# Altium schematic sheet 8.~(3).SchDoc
size 609 x 444 mm
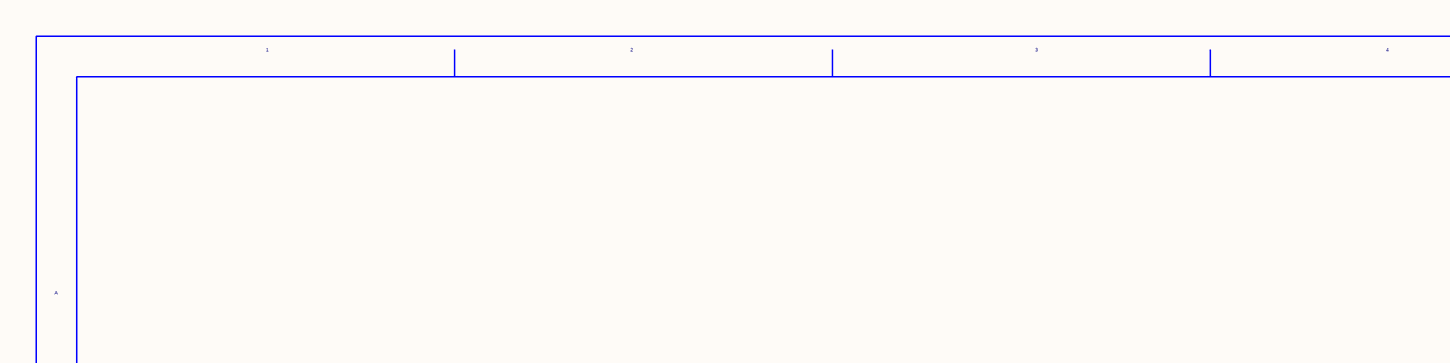
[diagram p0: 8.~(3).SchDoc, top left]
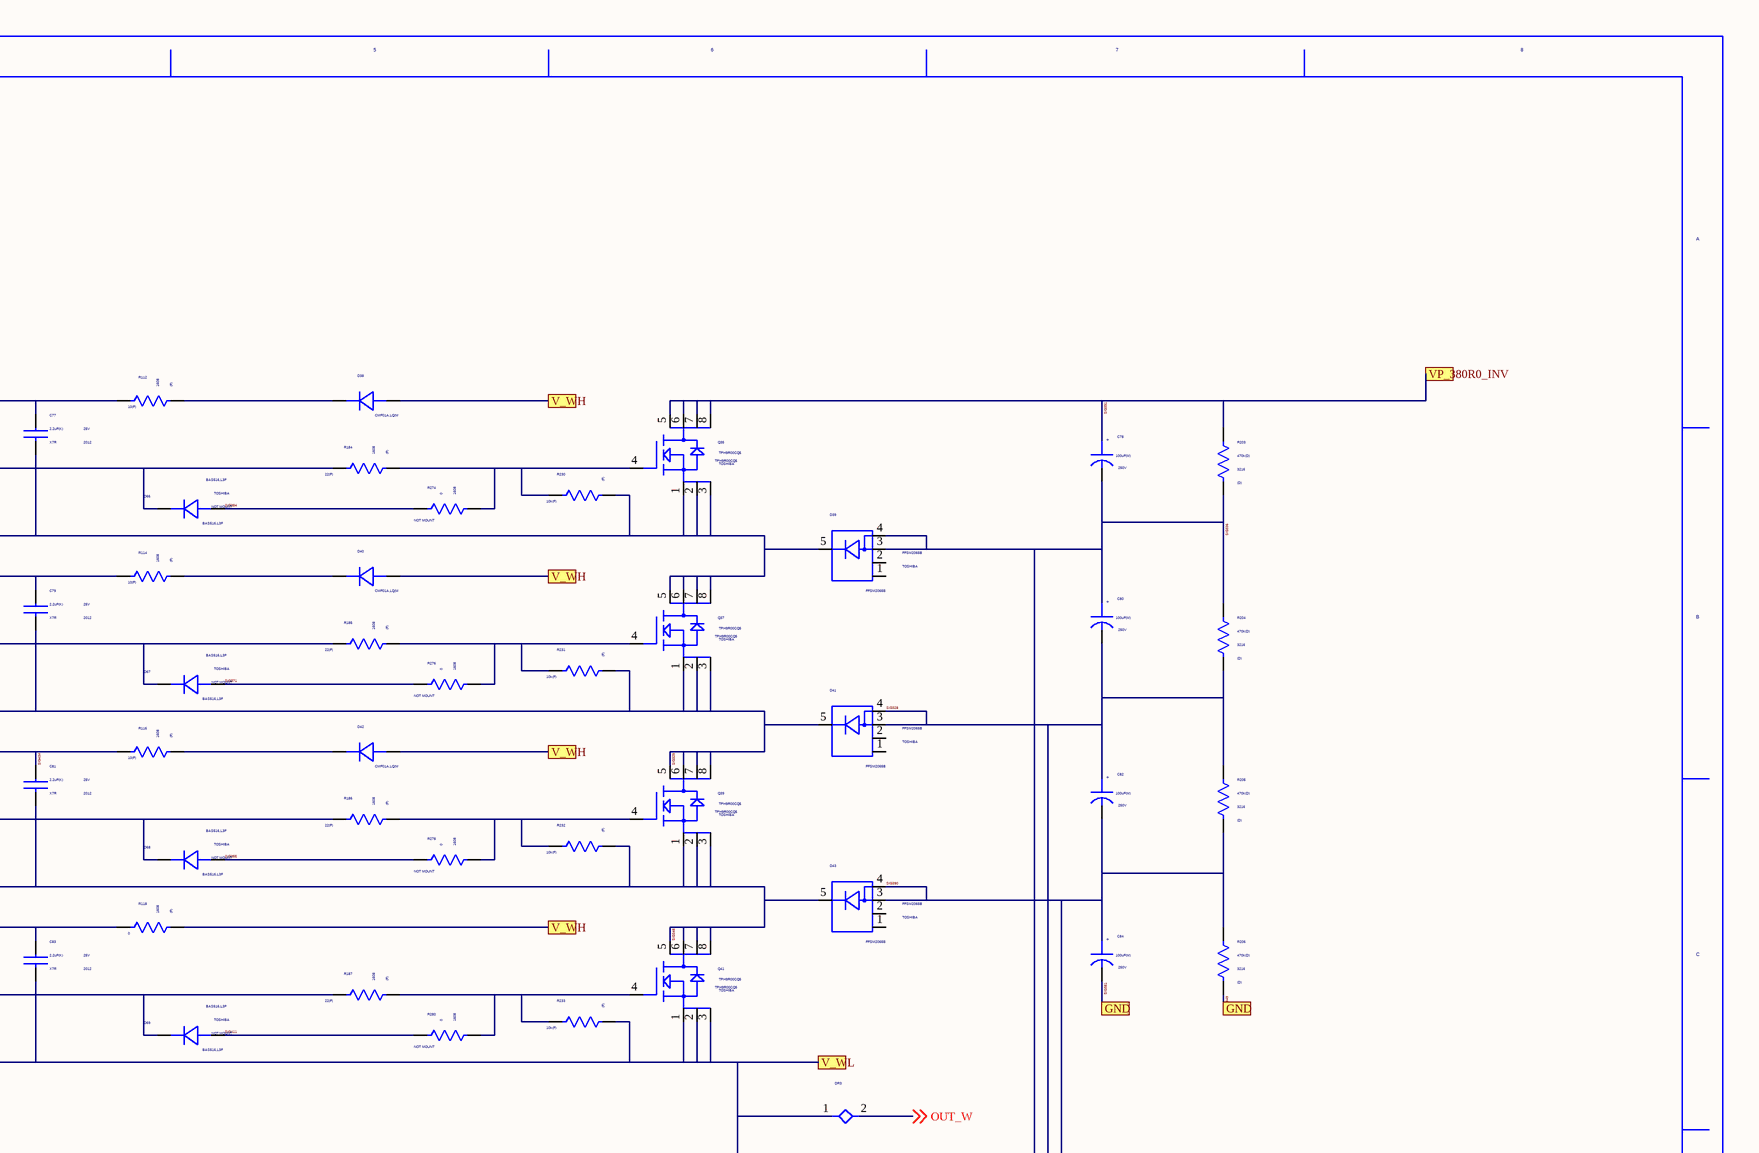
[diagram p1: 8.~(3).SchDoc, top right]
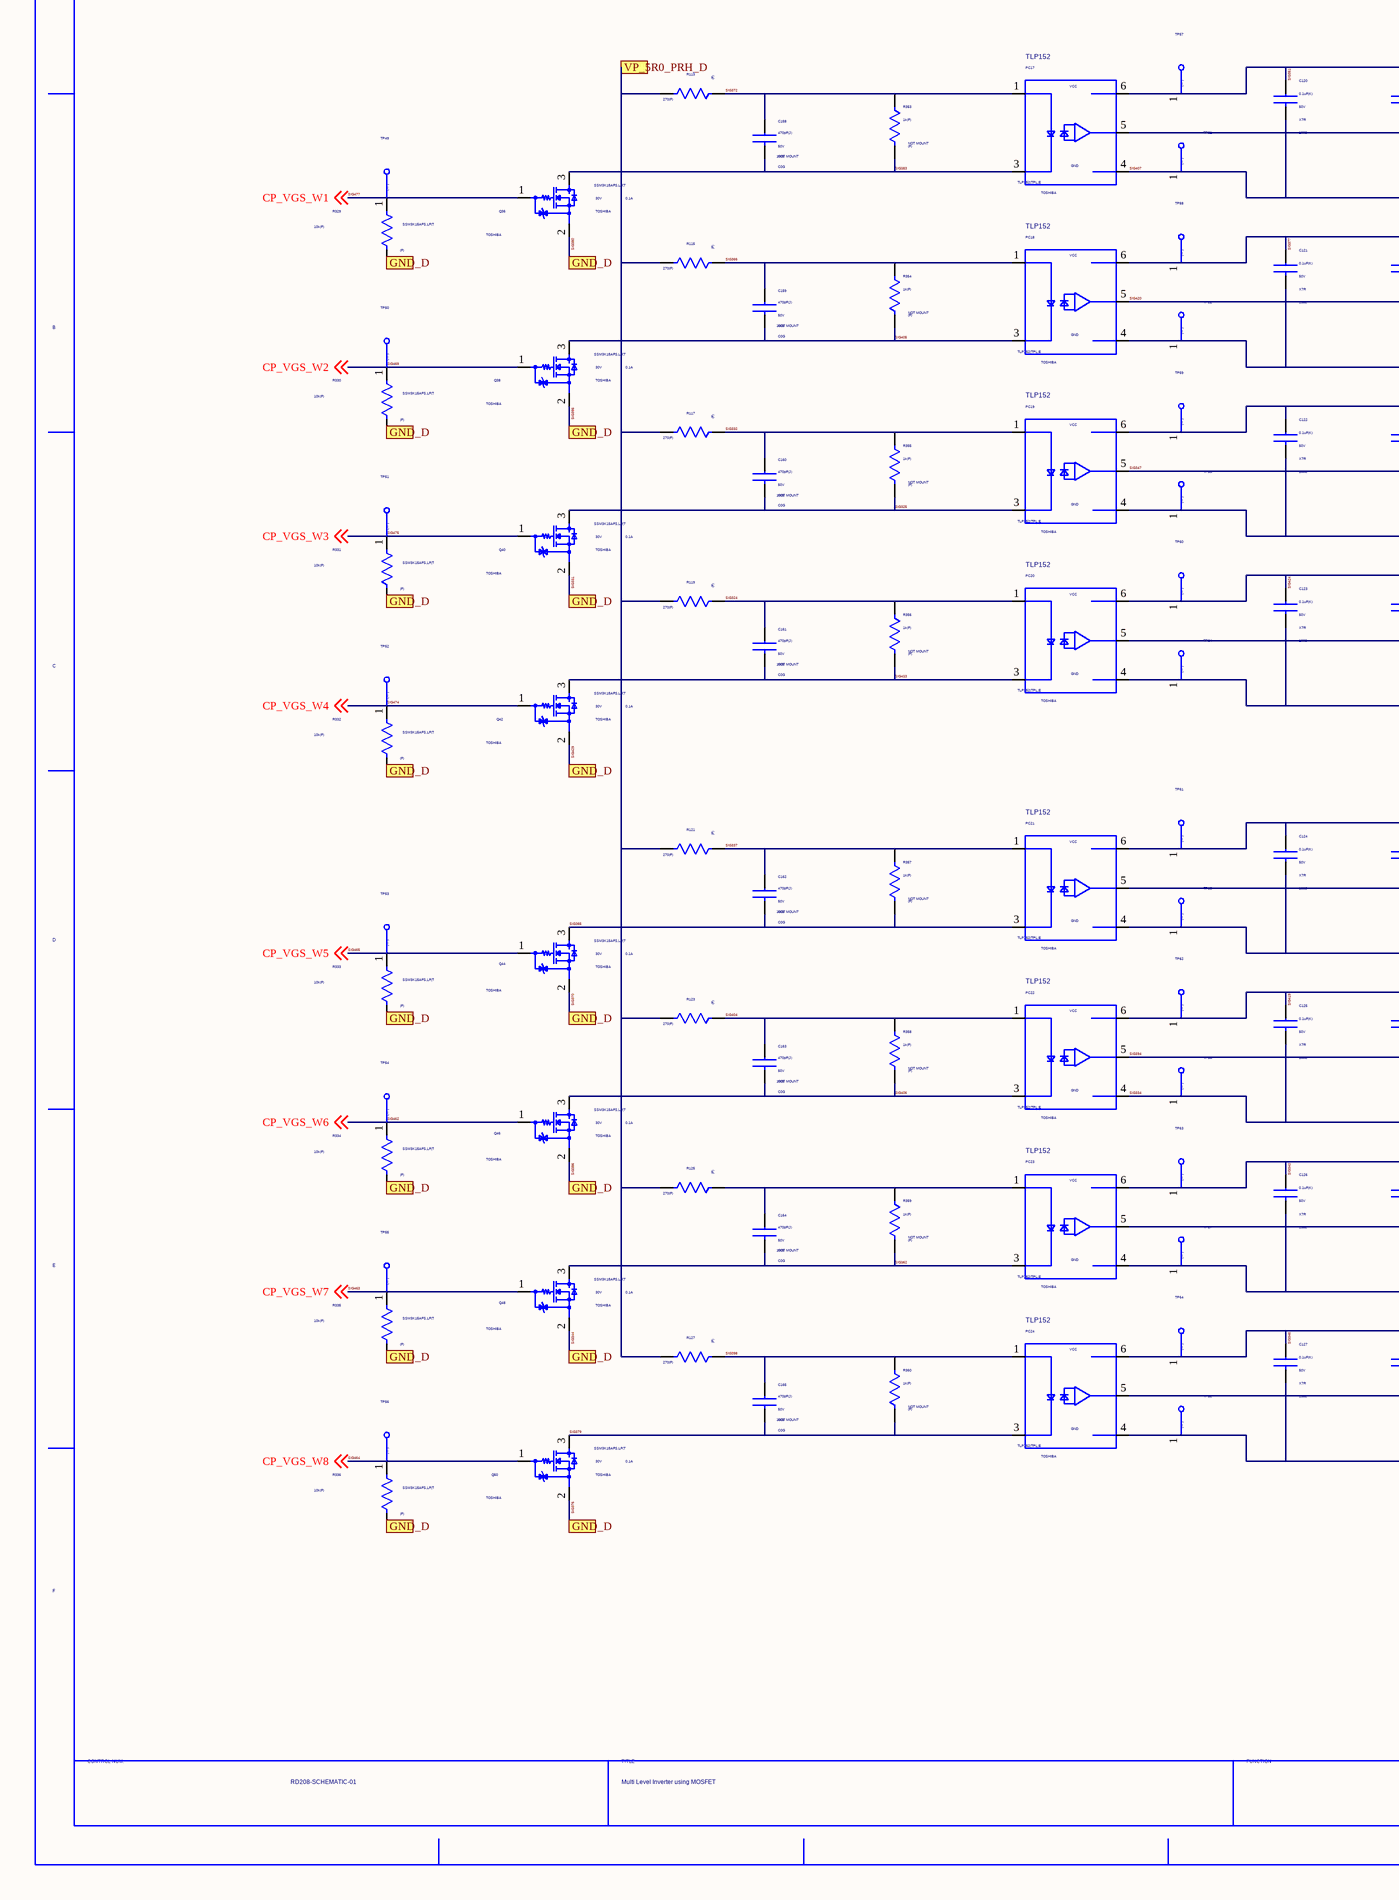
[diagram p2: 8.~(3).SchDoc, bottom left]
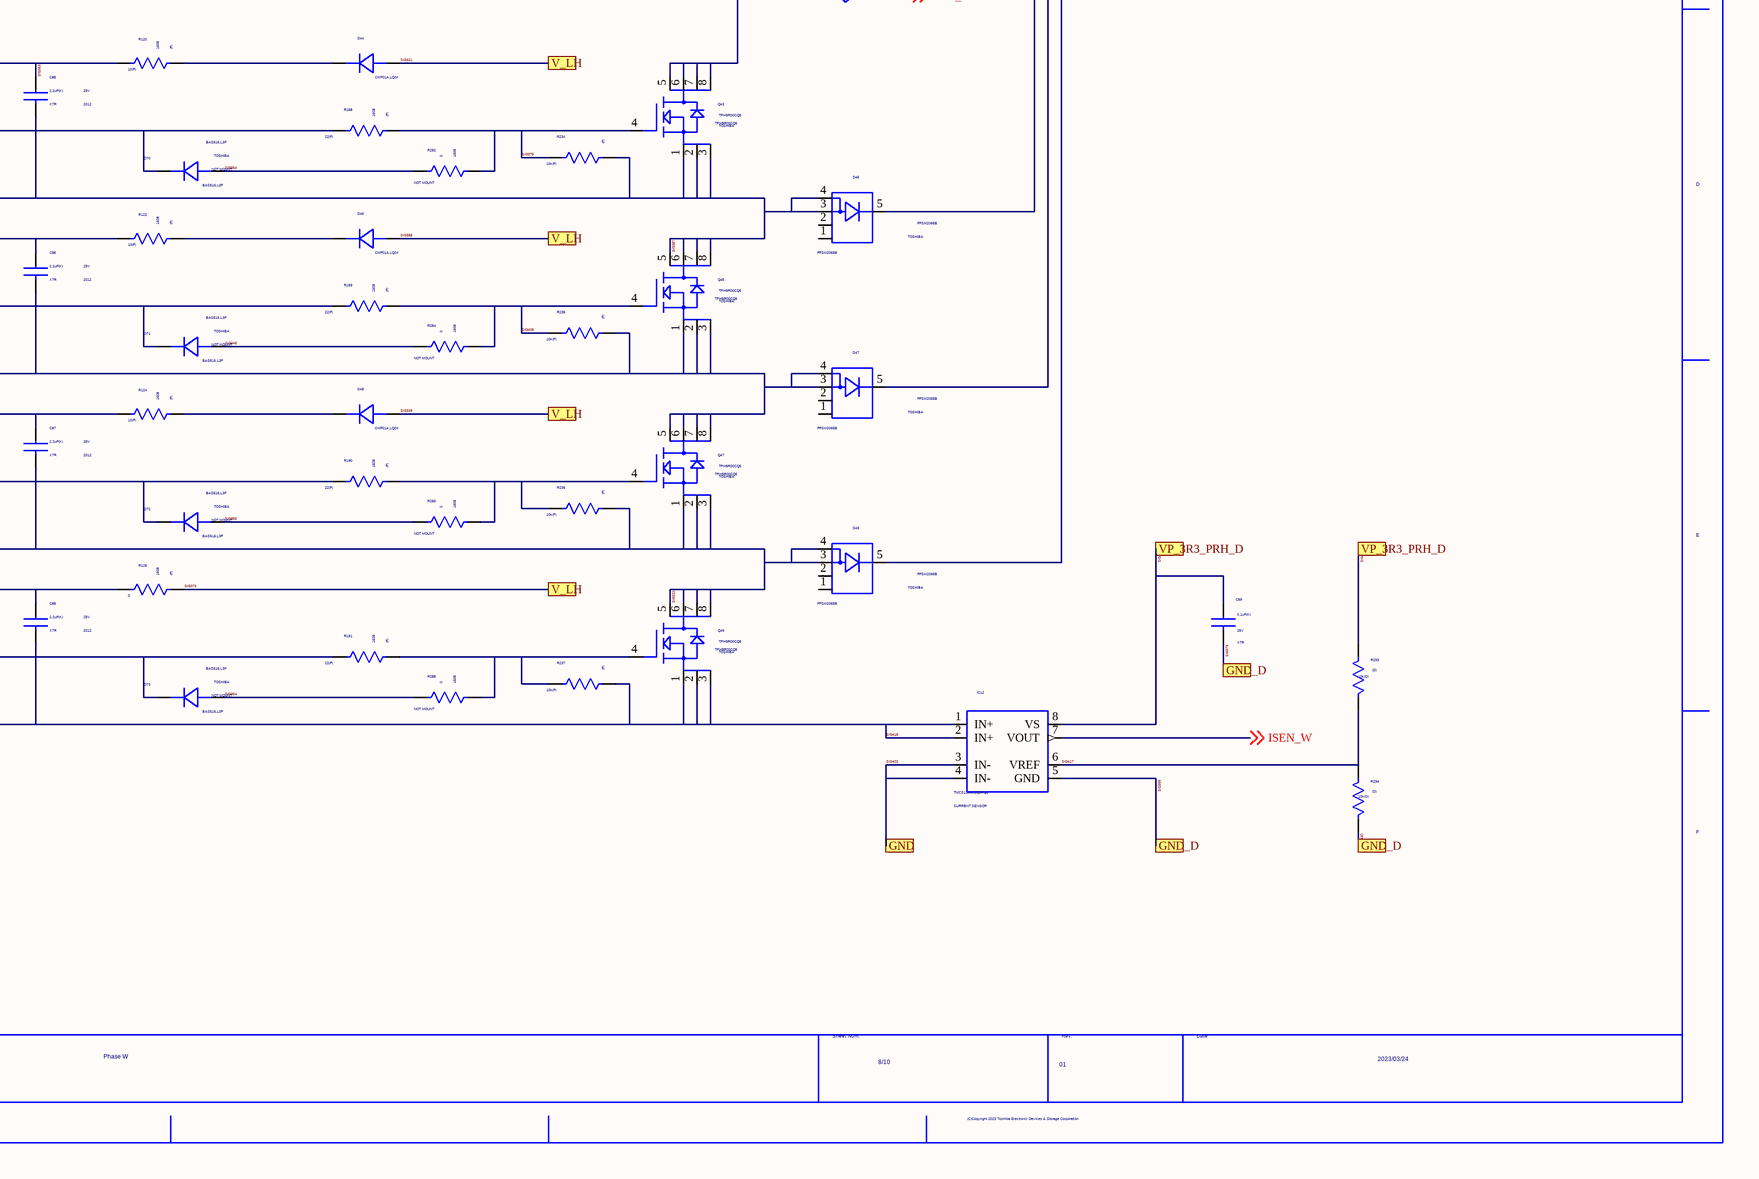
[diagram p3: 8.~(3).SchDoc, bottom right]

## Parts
C77  VAL2: 25V  SIZECODESMD: 2012  VALUE4: X7R  VAL1: 2.2uF(K)  (hidden comment: GRM21BR71E225KE11L)
C78  VAL2: 250V  VAL1: 100uF(M)  (hidden comment: EKMQ251ELL101ML25S)
C79  VAL2: 25V  SIZECODESMD: 2012  VALUE4: X7R  VAL1: 2.2uF(K)  (hidden comment: GRM21BR71E225KE11L)
C80  VAL2: 250V  VAL1: 100uF(M)  (hidden comment: EKMQ251ELL101ML25S)
C81  VAL2: 25V  SIZECODESMD: 2012  VALUE4: X7R  VAL1: 2.2uF(K)  (hidden comment: GRM21BR71E225KE11L)
C82  VAL2: 250V  VAL1: 100uF(M)  (hidden comment: EKMQ251ELL101ML25S)
C83  VAL2: 25V  SIZECODESMD: 2012  VALUE4: X7R  VAL1: 2.2uF(K)  (hidden comment: GRM21BR71E225KE11L)
C84  VAL2: 250V  VAL1: 100uF(M)  (hidden comment: EKMQ251ELL101ML25S)
C85  VAL2: 25V  SIZECODESMD: 2012  VALUE4: X7R  VAL1: 2.2uF(K)  (hidden comment: GRM21BR71E225KE11L)
C86  VAL2: 25V  SIZECODESMD: 2012  VALUE4: X7R  VAL1: 2.2uF(K)  (hidden comment: GRM21BR71E225KE11L)
C87  VAL2: 25V  SIZECODESMD: 2012  VALUE4: X7R  VAL1: 2.2uF(K)  (hidden comment: GRM21BR71E225KE11L)
C88  VAL2: 25V  SIZECODESMD: 2012  VALUE4: X7R  VAL1: 2.2uF(K)  (hidden comment: GRM21BR71E225KE11L)
C89  VAL2: 25V  VALUE4: X7R  VAL1: 0.1uF(K)  (hidden comment: GRM155R71E104KE14D)
C120  VAL2: 50V  SIZECODESMD: 1608  VALUE4: X7R  VAL1: 0.1uF(K)  (hidden comment: C1608X7R1H104K080AA)
C121  VAL2: 50V  SIZECODESMD: 1608  VALUE4: X7R  VAL1: 0.1uF(K)  (hidden comment: C1608X7R1H104K080AA)
C122  VAL2: 50V  SIZECODESMD: 1608  VALUE4: X7R  VAL1: 0.1uF(K)  (hidden comment: C1608X7R1H104K080AA)
C123  VAL2: 50V  SIZECODESMD: 1608  VALUE4: X7R  VAL1: 0.1uF(K)  (hidden comment: C1608X7R1H104K080AA)
C124  VAL2: 50V  SIZECODESMD: 1608  VALUE4: X7R  VAL1: 0.1uF(K)  (hidden comment: C1608X7R1H104K080AA)
C125  VAL2: 50V  SIZECODESMD: 1608  VALUE4: X7R  VAL1: 0.1uF(K)  (hidden comment: C1608X7R1H104K080AA)
C126  VAL2: 50V  SIZECODESMD: 1608  VALUE4: X7R  VAL1: 0.1uF(K)  (hidden comment: C1608X7R1H104K080AA)
C127  VAL2: 50V  SIZECODESMD: 1608  VALUE4: X7R  VAL1: 0.1uF(K)  (hidden comment: C1608X7R1H104K080AA)
C158  VAL2: 50V  SIZECODESMD: 1005  VALUE4: C0G  VAL1: 470pF(J)  NOTMOUNT: NOT MOUNT  (hidden comment: GRM1555C1H471JA01J)
C159  VAL2: 50V  SIZECODESMD: 1005  VALUE4: C0G  VAL1: 470pF(J)  NOTMOUNT: NOT MOUNT  (hidden comment: GRM1555C1H471JA01J)
C160  VAL2: 50V  SIZECODESMD: 1005  VALUE4: C0G  VAL1: 470pF(J)  NOTMOUNT: NOT MOUNT  (hidden comment: GRM1555C1H471JA01J)
C161  VAL2: 50V  SIZECODESMD: 1005  VALUE4: C0G  VAL1: 470pF(J)  NOTMOUNT: NOT MOUNT  (hidden comment: GRM1555C1H471JA01J)
C162  VAL2: 50V  SIZECODESMD: 1005  VALUE4: C0G  VAL1: 470pF(J)  NOTMOUNT: NOT MOUNT  (hidden comment: GRM1555C1H471JA01J)
C163  VAL2: 50V  SIZECODESMD: 1005  VALUE4: C0G  VAL1: 470pF(J)  NOTMOUNT: NOT MOUNT  (hidden comment: GRM1555C1H471JA01J)
C164  VAL2: 50V  SIZECODESMD: 1005  VALUE4: C0G  VAL1: 470pF(J)  NOTMOUNT: NOT MOUNT  (hidden comment: GRM1555C1H471JA01J)
C165  VAL2: 50V  SIZECODESMD: 1005  VALUE4: C0G  VAL1: 470pF(J)  NOTMOUNT: NOT MOUNT  (hidden comment: GRM1555C1H471JA01J)
D38  VAL1: CMF01A,LQ(M  (hidden comment: CMF01A,LQ_M)
D39  USERCOMPTEXT3: TOSHIBA  (hidden comment: FFSM2065B)
D40  VAL1: CMF01A,LQ(M  (hidden comment: CMF01A,LQ_M)
D41  USERCOMPTEXT3: TOSHIBA  (hidden comment: FFSM2065B)
D42  VAL1: CMF01A,LQ(M  (hidden comment: CMF01A,LQ_M)
D43  USERCOMPTEXT3: TOSHIBA  (hidden comment: FFSM2065B)
D44  VAL1: CMF01A,LQ(M  (hidden comment: CMF01A,LQ_M)
D45  USERCOMPTEXT3: TOSHIBA  (hidden comment: FFSM2065B)
D46  VAL1: CMF01A,LQ(M  (hidden comment: CMF01A,LQ_M)
D47  USERCOMPTEXT3: TOSHIBA  (hidden comment: FFSM2065B)
D48  VAL1: CMF01A,LQ(M  (hidden comment: CMF01A,LQ_M)
D49  USERCOMPTEXT3: TOSHIBA  (hidden comment: FFSM2065B)
D66  USERCOMPTEXT3: TOSHIBA  NOTMOUNT: NOT MOUNT  (hidden comment: BAS516,L3F)
D67  USERCOMPTEXT3: TOSHIBA  NOTMOUNT: NOT MOUNT  (hidden comment: BAS516,L3F)
D68  USERCOMPTEXT3: TOSHIBA  NOTMOUNT: NOT MOUNT  (hidden comment: BAS516,L3F)
D69  USERCOMPTEXT3: TOSHIBA  NOTMOUNT: NOT MOUNT  (hidden comment: BAS516,L3F)
D70  USERCOMPTEXT3: TOSHIBA  NOTMOUNT: NOT MOUNT  (hidden comment: BAS516,L3F)
D71  USERCOMPTEXT3: TOSHIBA  NOTMOUNT: NOT MOUNT  (hidden comment: BAS516,L3F)
D72  USERCOMPTEXT3: TOSHIBA  NOTMOUNT: NOT MOUNT  (hidden comment: BAS516,L3F)
D73  USERCOMPTEXT3: TOSHIBA  NOTMOUNT: NOT MOUNT  (hidden comment: BAS516,L3F)
DR3  STAR2  (value not drawn)
IC12  VAL2: CURRENT SENSOR  (hidden comment: TMCS1100A1QDRQ1)
PC17  SCH_NAME: TLP152  USERCOMPTEXT3: TOSHIBA  VAL3: TLP152(TPL,E  (hidden comment: TLP152_TPL,E)
PC18  SCH_NAME: TLP152  USERCOMPTEXT3: TOSHIBA  VAL3: TLP152(TPL,E  (hidden comment: TLP152_TPL,E)
PC19  SCH_NAME: TLP152  USERCOMPTEXT3: TOSHIBA  VAL3: TLP152(TPL,E  (hidden comment: TLP152_TPL,E)
PC20  SCH_NAME: TLP152  USERCOMPTEXT3: TOSHIBA  VAL3: TLP152(TPL,E  (hidden comment: TLP152_TPL,E)
PC21  SCH_NAME: TLP152  USERCOMPTEXT3: TOSHIBA  VAL3: TLP152(TPL,E  (hidden comment: TLP152_TPL,E)
PC22  SCH_NAME: TLP152  USERCOMPTEXT3: TOSHIBA  VAL3: TLP152(TPL,E  (hidden comment: TLP152_TPL,E)
PC23  SCH_NAME: TLP152  USERCOMPTEXT3: TOSHIBA  VAL3: TLP152(TPL,E  (hidden comment: TLP152_TPL,E)
PC24  SCH_NAME: TLP152  USERCOMPTEXT3: TOSHIBA  VAL3: TLP152(TPL,E  (hidden comment: TLP152_TPL,E)
Q35  USERCOMPTEXT3: TOSHIBA  (hidden comment: TPH9R00CQ5)
Q36  VAL2: 0.1A  MANUFACTURER: TOSHIBA  SIZECODESMD: 30V  VAL1: SSM3K15AFS,LF(T  (hidden comment: SSM3K15AFS,LF_T)
Q37  USERCOMPTEXT3: TOSHIBA  (hidden comment: TPH9R00CQ5)
Q38  VAL2: 0.1A  MANUFACTURER: TOSHIBA  SIZECODESMD: 30V  VAL1: SSM3K15AFS,LF(T  (hidden comment: SSM3K15AFS,LF_T)
Q39  USERCOMPTEXT3: TOSHIBA  (hidden comment: TPH9R00CQ5)
Q40  VAL2: 0.1A  MANUFACTURER: TOSHIBA  SIZECODESMD: 30V  VAL1: SSM3K15AFS,LF(T  (hidden comment: SSM3K15AFS,LF_T)
Q41  USERCOMPTEXT3: TOSHIBA  (hidden comment: TPH9R00CQ5)
Q42  VAL2: 0.1A  MANUFACTURER: TOSHIBA  SIZECODESMD: 30V  VAL1: SSM3K15AFS,LF(T  (hidden comment: SSM3K15AFS,LF_T)
Q43  USERCOMPTEXT3: TOSHIBA  (hidden comment: TPH9R00CQ5)
Q44  VAL2: 0.1A  MANUFACTURER: TOSHIBA  SIZECODESMD: 30V  VAL1: SSM3K15AFS,LF(T  (hidden comment: SSM3K15AFS,LF_T)
Q45  USERCOMPTEXT3: TOSHIBA  (hidden comment: TPH9R00CQ5)
Q46  VAL2: 0.1A  MANUFACTURER: TOSHIBA  SIZECODESMD: 30V  VAL1: SSM3K15AFS,LF(T  (hidden comment: SSM3K15AFS,LF_T)
Q47  USERCOMPTEXT3: TOSHIBA  (hidden comment: TPH9R00CQ5)
Q48  VAL2: 0.1A  MANUFACTURER: TOSHIBA  SIZECODESMD: 30V  VAL1: SSM3K15AFS,LF(T  (hidden comment: SSM3K15AFS,LF_T)
Q49  USERCOMPTEXT3: TOSHIBA  (hidden comment: TPH9R00CQ5)
Q50  VAL2: 0.1A  MANUFACTURER: TOSHIBA  SIZECODESMD: 30V  VAL1: SSM3K15AFS,LF(T  (hidden comment: SSM3K15AFS,LF_T)
R112  SIZECODESMD: 1608  VALUE4: (F)  VAL1: 10(F)  (hidden comment: ERJ3EKF10R0V)
R113  VALUE4: (F)  VAL1: 270(F)  (hidden comment: ERJ2RKF2700X)
R114  SIZECODESMD: 1608  VALUE4: (F)  VAL1: 10(F)  (hidden comment: ERJ3EKF10R0V)
R115  VALUE4: (F)  VAL1: 270(F)  (hidden comment: ERJ2RKF2700X)
R116  SIZECODESMD: 1608  VALUE4: (F)  VAL1: 10(F)  (hidden comment: ERJ3EKF10R0V)
R117  VALUE4: (F)  VAL1: 270(F)  (hidden comment: ERJ2RKF2700X)
R118  SIZECODESMD: 1608  VALUE4: (F)  VAL1: 0  (hidden comment: ERJ3EKF10R0V)
R119  VALUE4: (F)  VAL1: 270(F)  (hidden comment: ERJ2RKF2700X)
R120  SIZECODESMD: 1608  VALUE4: (F)  VAL1: 10(F)  (hidden comment: ERJ3EKF10R0V)
R121  VALUE4: (F)  VAL1: 270(F)  (hidden comment: ERJ2RKF2700X)
R122  SIZECODESMD: 1608  VALUE4: (F)  VAL1: 10(F)  (hidden comment: ERJ3EKF10R0V)
R123  VALUE4: (F)  VAL1: 270(F)  (hidden comment: ERJ2RKF2700X)
R124  SIZECODESMD: 1608  VALUE4: (F)  VAL1: 10(F)  (hidden comment: ERJ3EKF10R0V)
R125  VALUE4: (F)  VAL1: 270(F)  (hidden comment: ERJ2RKF2700X)
R126  SIZECODESMD: 1608  VALUE4: (F)  VAL1: 0  (hidden comment: ERJ3EKF10R0V)
R127  VALUE4: (F)  VAL1: 270(F)  (hidden comment: ERJ2RKF2700X)
R184  SIZECODESMD: 1608  VALUE4: (F)  VAL1: 22(F)  (hidden comment: ERJ3EKF22R0V)
R185  SIZECODESMD: 1608  VALUE4: (F)  VAL1: 22(F)  (hidden comment: ERJ3EKF22R0V)
R186  SIZECODESMD: 1608  VALUE4: (F)  VAL1: 22(F)  (hidden comment: ERJ3EKF22R0V)
R187  SIZECODESMD: 1608  VALUE4: (F)  VAL1: 22(F)  (hidden comment: ERJ3EKF22R0V)
R188  SIZECODESMD: 1608  VALUE4: (F)  VAL1: 22(F)  (hidden comment: ERJ3EKF22R0V)
R189  SIZECODESMD: 1608  VALUE4: (F)  VAL1: 22(F)  (hidden comment: ERJ3EKF22R0V)
R190  SIZECODESMD: 1608  VALUE4: (F)  VAL1: 22(F)  (hidden comment: ERJ3EKF22R0V)
R191  SIZECODESMD: 1608  VALUE4: (F)  VAL1: 22(F)  (hidden comment: ERJ3EKF22R0V)
R203  SIZECODESMD: 3216  VALUE4: (D)  VAL1: 470k(D)  (hidden comment: HV73V2BTTD4703D)
R204  SIZECODESMD: 3216  VALUE4: (D)  VAL1: 470k(D)  (hidden comment: HV73V2BTTD4703D)
R205  SIZECODESMD: 3216  VALUE4: (D)  VAL1: 470k(D)  (hidden comment: HV73V2BTTD4703D)
R206  SIZECODESMD: 3216  VALUE4: (D)  VAL1: 470k(D)  (hidden comment: HV73V2BTTD4703D)
R230  VALUE4: (F)  VAL1: 10k(F)  (hidden comment: ERJ2RKF1002X)
R231  VALUE4: (F)  VAL1: 10k(F)  (hidden comment: ERJ2RKF1002X)
R232  VALUE4: (F)  VAL1: 10k(F)  (hidden comment: ERJ2RKF1002X)
R233  VALUE4: (F)  VAL1: 10k(F)  (hidden comment: ERJ2RKF1002X)
R234  VALUE4: (F)  VAL1: 10k(F)  (hidden comment: ERJ2RKF1002X)
R235  VALUE4: (F)  VAL1: 10k(F)  (hidden comment: ERJ2RKF1002X)
R236  VALUE4: (F)  VAL1: 10k(F)  (hidden comment: ERJ2RKF1002X)
R237  VALUE4: (F)  VAL1: 10k(F)  (hidden comment: ERJ2RKF1002X)
R274  SIZECODESMD: 1608  VAL1: 0  NOTMOUNT: NOT MOUNT  (hidden comment: ERJ3GEY0R00V)
R276  SIZECODESMD: 1608  VAL1: 0  NOTMOUNT: NOT MOUNT  (hidden comment: ERJ3GEY0R00V)
R278  SIZECODESMD: 1608  VAL1: 0  NOTMOUNT: NOT MOUNT  (hidden comment: ERJ3GEY0R00V)
R280  SIZECODESMD: 1608  VAL1: 0  NOTMOUNT: NOT MOUNT  (hidden comment: ERJ3GEY0R00V)
R282  SIZECODESMD: 1608  VAL1: 0  NOTMOUNT: NOT MOUNT  (hidden comment: ERJ3GEY0R00V)
R284  SIZECODESMD: 1608  VAL1: 0  NOTMOUNT: NOT MOUNT  (hidden comment: ERJ3GEY0R00V)
R286  SIZECODESMD: 1608  VAL1: 0  NOTMOUNT: NOT MOUNT  (hidden comment: ERJ3GEY0R00V)
R288  SIZECODESMD: 1608  VAL1: 0  NOTMOUNT: NOT MOUNT  (hidden comment: ERJ3GEY0R00V)
R293  VALUE4: (D)  VAL1: 10k(D)  (hidden comment: RK73G1ETTP1002D)
R294  VALUE4: (D)  VAL1: 10k(D)  (hidden comment: RK73G1ETTP1002D)
R329  VALUE4: (F)  VAL1: 10k(F)  (hidden comment: ERJ2RKF1002X)
R330  VALUE4: (F)  VAL1: 10k(F)  (hidden comment: ERJ2RKF1002X)
R331  VALUE4: (F)  VAL1: 10k(F)  (hidden comment: ERJ2RKF1002X)
R332  VALUE4: (F)  VAL1: 10k(F)  (hidden comment: ERJ2RKF1002X)
R333  VALUE4: (F)  VAL1: 10k(F)  (hidden comment: ERJ2RKF1002X)
R334  VALUE4: (F)  VAL1: 10k(F)  (hidden comment: ERJ2RKF1002X)
R335  VALUE4: (F)  VAL1: 10k(F)  (hidden comment: ERJ2RKF1002X)
R336  VALUE4: (F)  VAL1: 10k(F)  (hidden comment: ERJ2RKF1002X)
R353  VALUE4: (F)  VAL1: 1k(F)  NOTMOUNT: NOT MOUNT  (hidden comment: ERJ2RKF1001X)
R354  VALUE4: (F)  VAL1: 1k(F)  NOTMOUNT: NOT MOUNT  (hidden comment: ERJ2RKF1001X)
R355  VALUE4: (F)  VAL1: 1k(F)  NOTMOUNT: NOT MOUNT  (hidden comment: ERJ2RKF1001X)
R356  VALUE4: (F)  VAL1: 1k(F)  NOTMOUNT: NOT MOUNT  (hidden comment: ERJ2RKF1001X)
R357  VALUE4: (F)  VAL1: 1k(F)  NOTMOUNT: NOT MOUNT  (hidden comment: ERJ2RKF1001X)
R358  VALUE4: (F)  VAL1: 1k(F)  NOTMOUNT: NOT MOUNT  (hidden comment: ERJ2RKF1001X)
R359  VALUE4: (F)  VAL1: 1k(F)  NOTMOUNT: NOT MOUNT  (hidden comment: ERJ2RKF1001X)
R360  VALUE4: (F)  VAL1: 1k(F)  NOTMOUNT: NOT MOUNT  (hidden comment: ERJ2RKF1001X)
TP49  TP  (value not drawn)
TP50  TP  (value not drawn)
TP51  TP  (value not drawn)
TP52  TP  (value not drawn)
TP53  TP  (value not drawn)
TP54  TP  (value not drawn)
TP55  TP  (value not drawn)
TP56  TP  (value not drawn)
TP57  TP  (value not drawn)
TP58  TP  (value not drawn)
TP59  TP  (value not drawn)
TP60  TP  (value not drawn)
TP61  TP  (value not drawn)
TP62  TP  (value not drawn)
TP63  TP  (value not drawn)
TP64  TP  (value not drawn)
TP81  TP  (value not drawn)
TP82  TP  (value not drawn)
TP83  TP  (value not drawn)
TP84  TP  (value not drawn)
TP85  TP  (value not drawn)
TP86  TP  (value not drawn)
TP87  TP  (value not drawn)
TP88  TP  (value not drawn)
U?  DATE: 2023/03/24  TITLE: Multi Level Inverter using MOSFET  REVISION: 01  SHEETNUMBER: 8/10  DRAWINGNUMBER: RD208-SCHEMATIC-01  FUNCTION: Phase W  (hidden comment: WAKU_DEF_A3)

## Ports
GND, GND_D, V_LH, V_WH, V_WL, VP_3R3_PRH_D, VP_5R0_PRH_D, VP_380R0_INV

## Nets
ISEN_W: IC12.7(VOUT) ; off-sheet ISEN_W
OUT_W: DR3.2 ; off-sheet OUT_W
SIG324: C161.1 PC20.1 R119.2 R356.1
SIG325: C160.2 PC19.3 Q40.3(C) R355.2
SIG326: D42.K(CATHODE) R116.2
SIG327: D70.K(CATHODE) PC21.5 R188.1
SIG328: C80.2 C82.1 D41.3(ANODE3) D41.4(ANODE4) D47.5(CATHODE) R204.2 R205.1
SIG329: C79.2 C121.2 D41.5(CATHODE) PC18.4 Q37.1(S1) Q37.2(S2) Q37.3(S3) Q39.5(D1) Q39.6(D2) Q39.7(D3) Q39.8(D4) R231.2 TP82.1
SIG331: C89.2 IC12.5(GND) Q36.2(E) Q38.2(E) Q40.2(E) Q42.2(E) Q44.2(E) Q46.2(E) Q48.2(E) Q50.2(E) R294.1 R329.2 R330.2 R331.2 R332.2 R333.2 R334.2 R335.2 R336.2 ; port GND_D  [also labelled SIG344, SIG370, SIG376, SIG378, SIG380, SIG386, SIG395, SIG399, SIG429, SIG430]
SIG332: C160.1 PC19.1 R117.2 R355.1
SIG333: C87.2 C126.2 D49.3(ANODE3) D49.4(ANODE4) PC23.4 Q47.1(S1) Q47.2(S2) Q47.3(S3) Q49.5(D1) Q49.6(D2) Q49.7(D3) Q49.8(D4) R236.2 TP87.1
SIG334: C86.2 C125.2 D47.3(ANODE3) D47.4(ANODE4) PC22.4 Q45.1(S1) Q45.2(S2) Q45.3(S3) Q47.5(D1) Q47.6(D2) Q47.7(D3) Q47.8(D4) R235.2 TP86.1
SIG336: C78.2 C80.1 D39.3(ANODE3) D39.4(ANODE4) D45.5(CATHODE) R203.2 R204.1
SIG337: C162.1 PC21.1 R121.2 R357.1
SIG338: C164.1 PC23.1 R125.2 R359.1
SIG339: D44.A(ANODE) D46.A(ANODE) D48.A(ANODE) R126.2 ; port V_LH  [also labelled SIG373, SIG388, SIG421]
SIG340: Q47.4(G) R190.2 R236.1 R286.2
SIG343: C87.1 C126.1 PC23.6 R124.1 TP63.1
SIG345: D71.A(ANODE) R284.1
SIG346: C88.1 C127.1 PC24.6 R126.1 TP64.1
SIG347: D68.K(CATHODE) PC19.5 R186.1
SIG348: C81.2 C122.2 D43.5(CATHODE) PC19.4 Q39.1(S1) Q39.2(S2) Q39.3(S3) Q41.5(D1) Q41.6(D2) Q41.7(D3) Q41.8(D4) R232.2 TP83.1
SIG349: C84.2 IC12.3(IN-) IC12.4(IN-) R206.2 ; port GND  [also labelled SIG381, SIG402]
SIG350: D38.K(CATHODE) R112.2
SIG351: C77.1 C120.1 PC17.6 R112.1 TP57.1
SIG352: Q35.4(G) R184.2 R230.1 R274.2
SIG353: D44.K(CATHODE) R120.2
SIG354: D70.A(ANODE) R282.1
SIG355: D68.A(ANODE) R278.1
SIG356: D72.A(ANODE) R286.1
SIG362: C164.2 PC23.3 Q48.3(C) R359.2
SIG363: C85.1 C124.1 PC21.6 R120.1 TP61.1
SIG364: D73.A(ANODE) R288.1
SIG365: C162.2 PC21.3 Q44.3(C) R357.2
SIG366: C159.1 PC18.1 R115.2 R354.1
SIG367: D66.K(CATHODE) PC17.5 R184.1
SIG371: D67.A(ANODE) R276.1
SIG372: C158.1 PC17.1 R113.2 R353.1
SIG374: D73.K(CATHODE) PC24.5 R191.1
SIG375: Q43.4(G) R188.2 R234.1 R282.2
SIG377: C79.1 C121.1 PC18.6 R114.1 TP58.1
SIG379: C165.2 PC24.3 Q50.3(C) R360.2
SIG382: Q49.4(G) R191.2 R237.1 R288.2
SIG383: C158.2 PC17.3 Q36.3(C) R353.2
SIG384: D66.A(ANODE) R274.1
SIG387: C85.2 C124.2 D45.3(ANODE3) D45.4(ANODE4) PC21.4 Q43.1(S1) Q43.2(S2) Q43.3(S3) Q45.5(D1) Q45.6(D2) Q45.7(D3) Q45.8(D4) R234.2 TP85.1
SIG389: D48.K(CATHODE) R124.2
SIG390: C82.2 C84.1 D43.3(ANODE3) D43.4(ANODE4) D49.5(CATHODE) R205.2 R206.1
SIG391: C78.1 Q35.5(D1) Q35.6(D2) Q35.7(D3) Q35.8(D4) R203.1 ; port VP_380R0_INV
SIG394: D71.K(CATHODE) PC22.5 R189.1
SIG398: C165.1 PC24.1 R127.2 R360.1
SIG401: C89.1 IC12.8(VS) R293.2 ; port VP_3R3_PRH_D  [also labelled SIG415]
SIG403: D69.K(CATHODE) PC20.5 R187.1
SIG404: C163.1 PC22.1 R123.2 R358.1
SIG405: C159.2 PC18.3 Q38.3(C) R354.2
SIG406: C163.2 PC22.3 Q46.3(C) R358.2
SIG407: C77.2 C120.2 D39.5(CATHODE) PC17.4 Q35.1(S1) Q35.2(S2) Q35.3(S3) Q37.5(D1) Q37.6(D2) Q37.7(D3) Q37.8(D4) R230.2 TP81.1
SIG408: Q45.4(G) R189.2 R235.1 R284.2
SIG409: Q37.4(G) R185.2 R231.1 R276.2
SIG410: Q39.4(G) R186.2 R232.1 R278.2
SIG411: D69.A(ANODE) R280.1
SIG413: D40.K(CATHODE) R114.2
SIG417: IC12.6(VREF) R293.1 R294.2
SIG418: C88.2 C127.2 IC12.1(IN+) IC12.2(IN+) PC24.4 Q49.1(S1) Q49.2(S2) Q49.3(S3) R237.2 TP88.1
SIG419: C86.1 C125.1 PC22.6 R122.1 TP62.1
SIG420: D67.K(CATHODE) PC18.5 R185.1
SIG423: D72.K(CATHODE) PC23.5 R190.1
SIG424: C83.1 C123.1 PC20.6 R118.1 TP60.1
SIG425: D46.K(CATHODE) R122.2
SIG426: Q41.4(G) R187.2 R233.1 R280.2
SIG433: C161.2 PC20.3 Q42.3(C) R356.2
SIG434: C81.1 C122.1 PC19.6 R116.1 TP59.1
SIG462: Q46.1(B) R334.1 TP54.1 ; off-sheet CP_VGS_W6  [also labelled CP_VGS_W6]
SIG463: Q48.1(B) R335.1 TP55.1 ; off-sheet CP_VGS_W7  [also labelled CP_VGS_W7]
SIG464: Q50.1(B) R336.1 TP56.1 ; off-sheet CP_VGS_W8  [also labelled CP_VGS_W8]
SIG465: Q44.1(B) R333.1 TP53.1 ; off-sheet CP_VGS_W5  [also labelled CP_VGS_W5]
SIG469: Q38.1(B) R330.1 TP50.1 ; off-sheet CP_VGS_W2  [also labelled CP_VGS_W2]
SIG474: Q42.1(B) R332.1 TP52.1 ; off-sheet CP_VGS_W4  [also labelled CP_VGS_W4]
SIG475: Q40.1(B) R331.1 TP51.1 ; off-sheet CP_VGS_W3  [also labelled CP_VGS_W3]
SIG477: Q36.1(B) R329.1 TP49.1 ; off-sheet CP_VGS_W1  [also labelled CP_VGS_W1]
V_WH: D38.A(ANODE) D40.A(ANODE) D42.A(ANODE) R118.2 ; port V_WH
V_WL: C83.2 C123.2 DR3.1 PC20.4 Q41.1(S1) Q41.2(S2) Q41.3(S3) Q43.5(D1) Q43.6(D2) Q43.7(D3) Q43.8(D4) R233.2 TP84.1 ; port V_WL
VP_5R0_PRH_D: R113.1 R115.1 R117.1 R119.1 R121.1 R123.1 R125.1 R127.1 ; port VP_5R0_PRH_D

Not connected (* = marked no-connect by the designer): D39 1(NC1) 2(NC2); D41 1(NC1) 2(NC2); D43 1(NC1) 2(NC2); D45 1(NC1) 2(NC2); D47 1(NC1) 2(NC2); D49 1(NC1) 2(NC2)

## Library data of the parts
C77 C79 C81 C83 C85-C88 = GRM21BR71E225KE11L: MANUFACTURER: MURATA; ITEM: CAP Ceramic; TIME: 08:44:45; UPDATEUSER: t5459927; SAVECOUNT: 1; OriginalSymbolOrigin: (0,0); INSTANCENAME: INS15860000
C78 = EKMQ251ELL101ML25S: MANUFACTURER: Nippon Chemi-Con; ITEM: CAP ALUM; TIME: 08:44:45; UPDATEUSER: t5459927; SAVECOUNT: 1; OriginalSymbolOrigin: (0,2540); INSTANCENAME: INS16070082
C80 = EKMQ251ELL101ML25S: MANUFACTURER: Nippon Chemi-Con; ITEM: CAP ALUM; TIME: 08:44:45; UPDATEUSER: t5459927; SAVECOUNT: 1; OriginalSymbolOrigin: (0,2540); INSTANCENAME: INS16070102
C82 = EKMQ251ELL101ML25S: MANUFACTURER: Nippon Chemi-Con; ITEM: CAP ALUM; TIME: 08:44:45; UPDATEUSER: t5459927; SAVECOUNT: 1; OriginalSymbolOrigin: (0,2540); INSTANCENAME: INS16070122
C84 = EKMQ251ELL101ML25S: MANUFACTURER: Nippon Chemi-Con; ITEM: CAP ALUM; TIME: 08:44:45; UPDATEUSER: t5459927; SAVECOUNT: 1; OriginalSymbolOrigin: (0,2540); INSTANCENAME: INS16070142
C89 = GRM155R71E104KE14D: MANUFACTURER: MURATA; ITEM: CAP Ceramic; SIZECODESMD: 1005; TIME: 08:44:45; UPDATEUSER: t5459927; SAVECOUNT: 1; OriginalSymbolOrigin: (0,0); INSTANCENAME: INS16776295
C120-C127 = C1608X7R1H104K080AA: MANUFACTURER: TDK; ITEM: CAP Ceramic; TIME: 08:44:45; UPDATEUSER: t5459927; SAVECOUNT: 1; OriginalSymbolOrigin: (0,0); INSTANCENAME: INS16097035
C158-C165 = GRM1555C1H471JA01J: MANUFACTURER: MURATA; ITEM: CAP Ceramic; TIME: 08:44:46; UPDATEUSER: t5459927; SAVECOUNT: 1; OriginalSymbolOrigin: (0,0); INSTANCENAME: INS17224098
D38 D40 D42 D44 D46 D48 = CMF01A,LQ_M: MANUFACTURER: TOSHIBA; COMP: CMF01A_LQ_M; ITEM: DIODE; TIME: 08:44:46; UPDATEUSER: t5459927; SAVECOUNT: 1; OriginalSymbolOrigin: (0,0); INSTANCENAME: INS15860772
D39 D41 D43 D45 D47 D49 = FFSM2065B: MANUFACTURER: ON_SEMI; ITEM: DIODE; TIME: 08:44:45; UPDATEUSER: t5459927; SAVECOUNT: 1; SAVEAREA0: -3235,-11101,10576,-990; OriginalSymbolOrigin: (0,0); INSTANCENAME: INS16711377
D66-D73 = BAS516,L3F: COMP: BAS516_L3F; ITEM: DIODE; TIME: 08:44:45; UPDATEUSER: t5459927; SAVECOUNT: 1; OriginalSymbolOrigin: (0,0); INSTANCENAME: INS16674713
DR3 = STAR2: TIME: 12:37:47; UPDATEUSER: d5009410; UPDATETIME: 12:51:51; SAVECOUNT: 17; SAVEAREA0: -6564,-5245,9999,5672; OriginalSymbolOrigin: (-2540,2540); COMP: ONEPOINT
IC12 = TMCS1100A1QDRQ1: MANUFACTURER: TI; ITEM: IC CurrentSensor; TIME: 08:44:45; UPDATEUSER: PS4_common_PC; UPDATETIME: 16:01:14; SAVECOUNT: 3; SAVEAREA0: -10605,-15555,25377,840; OriginalSymbolOrigin: (0,0)
PC17-PC24 = TLP152_TPL,E: ITEM: Photocoupler; COMP: TLP152_TPL_E; TIME: 08:44:45; UPDATEUSER: t5459927; SAVECOUNT: 1; OriginalSymbolOrigin: (0,0); INSTANCENAME: INS15861608
Q35 Q37 Q39 Q41 Q43 Q45 Q47 Q49 = TPH9R00CQ5: ITEM: FET; ORDER: 0; TIME: 08:44:45; UPDATEUSER: t5459927; SAVECOUNT: 1; OriginalSymbolOrigin: (0,0); INSTANCENAME: INS15860992
Q36 Q38 Q40 Q42 Q44 Q46 Q48 Q50 = SSM3K15AFS,LF_T: ITEM: Digital Transistor NPN; COMP: SSM3K15AFS-123; ORDER: 0; TIME: 08:44:45; UPDATEUSER: t5459927; SAVECOUNT: 1; OriginalSymbolOrigin: (0,0); INSTANCENAME: INS15859756
R112 R114 R116 R120 R122 R124 = ERJ3EKF10R0V: MANUFACTURER: Panasonic; ITEM: Register; VAL2: 100mW; TIME: 08:44:45; UPDATEUSER: t5459927; SAVECOUNT: 1; OriginalSymbolOrigin: (0,0); INSTANCENAME: INS16646496
R113 R115 R117 R119 R121 R123 R125 R127 = ERJ2RKF2700X: MANUFACTURER: Panasonic; ITEM: Register; VAL2: 100mW; SIZECODESMD: 1005; TIME: 08:44:45; UPDATEUSER: t5459927; SAVECOUNT: 1; OriginalSymbolOrigin: (0,0); INSTANCENAME: INS16151457
R118 R126 = ERJ3EKF10R0V: MANUFACTURER: Panasonic; ITEM: Register; VAL2: 1/10W; COMP: ERJ3GEY0R00V; TIME: 08:44:45; UPDATEUSER: t5459927; SAVECOUNT: 1; OriginalSymbolOrigin: (0,0); INSTANCENAME: INS16646496
R184-R191 = ERJ3EKF22R0V: MANUFACTURER: Panasonic; ITEM: Register; VAL2: 100mW; TIME: 08:44:45; UPDATEUSER: t5459927; SAVECOUNT: 1; OriginalSymbolOrigin: (0,0); INSTANCENAME: INS17210794
R203 = HV73V2BTTD4703D: MANUFACTURER: KOA; ITEM: Register; VAL2: 0.33W; TIME: 08:44:45; UPDATEUSER: t5459927; SAVECOUNT: 1; OriginalSymbolOrigin: (0,0); INSTANCENAME: INS16806843
R204 = HV73V2BTTD4703D: MANUFACTURER: KOA; ITEM: Register; VAL2: 0.33W; TIME: 08:44:45; UPDATEUSER: t5459927; SAVECOUNT: 1; OriginalSymbolOrigin: (0,0); INSTANCENAME: INS16806859
R205 = HV73V2BTTD4703D: MANUFACTURER: KOA; ITEM: Register; VAL2: 0.33W; TIME: 08:44:45; UPDATEUSER: t5459927; SAVECOUNT: 1; OriginalSymbolOrigin: (0,0); INSTANCENAME: INS16806875
R206 = HV73V2BTTD4703D: MANUFACTURER: KOA; ITEM: Register; VAL2: 0.33W; TIME: 08:44:45; UPDATEUSER: t5459927; SAVECOUNT: 1; OriginalSymbolOrigin: (0,0); INSTANCENAME: INS16806891
R230-R237 = ERJ2RKF1002X: MANUFACTURER: Panasonic; ITEM: Register; VAL2: 100mW; SIZECODESMD: 1005; TIME: 08:44:45; UPDATEUSER: t5459927; SAVECOUNT: 1; OriginalSymbolOrigin: (0,0); INSTANCENAME: INS16648754
R274 R276 R278 R280 R282 R284 R286 R288 = ERJ3GEY0R00V: MANUFACTURER: Panasonic; ITEM: Register; VAL2: 1/10W; TIME: 08:44:45; UPDATEUSER: t5459927; SAVECOUNT: 1; OriginalSymbolOrigin: (0,0); INSTANCENAME: INS16674743
R293 = RK73G1ETTP1002D: MANUFACTURER: KOA; ITEM: Register; VAL2: 100mW; SIZECODESMD: 1005; TIME: 08:44:46; UPDATEUSER: t5459927; SAVECOUNT: 1; OriginalSymbolOrigin: (0,0); INSTANCENAME: INS16808670
R294 = RK73G1ETTP1002D: MANUFACTURER: KOA; ITEM: Register; VAL2: 100mW; SIZECODESMD: 1005; TIME: 08:44:46; UPDATEUSER: t5459927; SAVECOUNT: 1; OriginalSymbolOrigin: (0,0); INSTANCENAME: INS16808683
R329-R336 = ERJ2RKF1002X: MANUFACTURER: Panasonic; ITEM: Register; VAL2: 100mW; SIZECODESMD: 1005; TIME: 08:44:45; UPDATEUSER: t5459927; SAVECOUNT: 1; OriginalSymbolOrigin: (0,0); INSTANCENAME: INS17222356
R353-R360 = ERJ2RKF1001X: MANUFACTURER: Panasonic; ITEM: Register; VAL2: 100mW; SIZECODESMD: 1005; TIME: 08:44:45; UPDATEUSER: t5459927; SAVECOUNT: 1; OriginalSymbolOrigin: (0,0); INSTANCENAME: INS17224061
TP49-TP64 TP81-TP88 = TP: TIME: 16:12:21; UPDATEUSER: fukuda-y; UPDATETIME: 16:18:11; SAVECOUNT: 2; SAVEAREA0: -242,-92,12810,7836; OriginalSymbolOrigin: (0,7620); VAL3: TH Hole dia. 1.0; COMP: TP-TH1.0-L1.6
U? = WAKU_DEF_A3: PLOTTIME: HH:MM; SAVEAREA0: -311037,-554865,914355,115662; TIME: 14:30:25; UPDATEUSER: PS4_common_PC; UPDATETIME: 08:25:56; SAVECOUNT: 18; ZONEOFFSETX: 36; ZONEOFFSETY: -24; OriginalSymbolOrigin: (12700,-12700)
